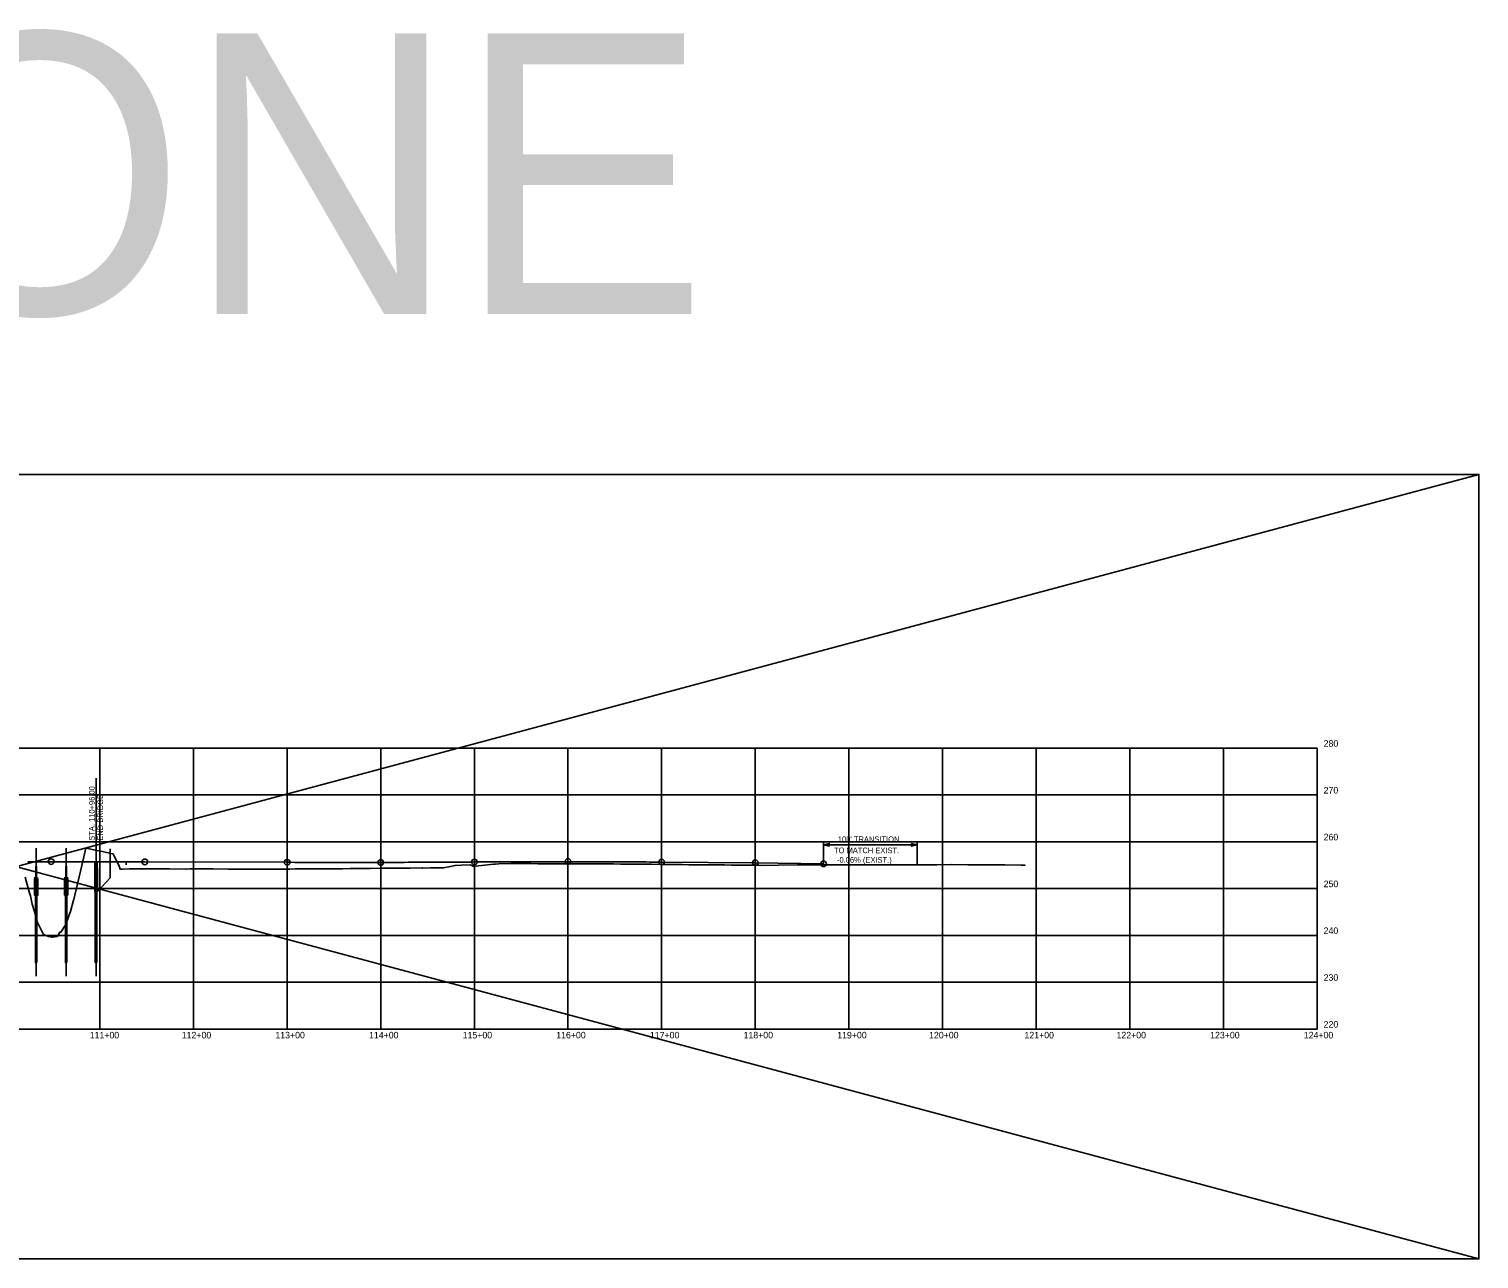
# Model space of a CAD drawing. Extents: x 1930770 to 1938778, y 596900 to 600561.
# Drawn here: x 1937230 to 1938778, y 598329 to 599642 of the extents above; entities that cross this region are included whole.
import ezdxf

# ---------------------------------------------------------------- set-up
doc = ezdxf.new("R2010")
doc.units = 0
for name, color, linetype in [('B_Centerline', 7, 'Continuous'), ('B_Pr_Beam_Line', 7, 'Continuous'), ('B_Pr_Cap_Beams', 7, 'Continuous'), ('B_Pr_Columns', 7, 'Continuous'), ('B_Pr_Deck', 7, 'Continuous'), ('BR_Pr_Cap_Beams', 7, 'Continuous'), ('Default', 7, 'Continuous'), ('S_CROSS_DRAIN_ANNOT', 7, 'Continuous'), ('S_DROP_INLET_ANNOT', 7, 'Continuous'), ('S_ELECTRIC_UTILITIES_ANNOT', 7, 'Continuous'), ('S_GAS_UTILITIES_ANNOT', 7, 'Continuous'), ('S_HIST_HIGH_WATER_ANNOT', 7, 'Continuous'), ('S_STORM_SEWER_ANNOT', 7, 'Continuous'), ('S_TELEPHONE_UTILITIES_ANNOT', 7, 'Continuous'), ('S_UTILITY_POLE_ANNOT', 7, 'Continuous'), ('S_WATER_UTILITIES_ANNOT', 7, 'Continuous')]:
    doc.layers.add(name, color=color, linetype=linetype)

msp = doc.modelspace()

# ---------------------------------------------------------------- linework, layer by layer
at = {"layer": 'B_Centerline'}
for p, q in [((1937237.2, 598631.1), (1937237.2, 598767.6)), ((1937269.2, 598631.1), (1937269.2, 598767.6)), ((1937301.2, 598631.1), (1937301.2, 598767.6))]:
    msp.add_line(p, q, dxfattribs=at)
at = {"layer": 'B_Pr_Beam_Line'}
msp.add_line((1937301.7, 598748.6), (1937301.7, 598736.9), dxfattribs=at)
at = {"layer": 'B_Pr_Cap_Beams'}
for p, q in [((1937237, 598736.6), (1937237, 598748.3)), ((1937237.5, 598736.6), (1937237.5, 598748.3)), ((1937269, 598736.8), (1937269, 598748.5)), ((1937269.5, 598736.8), (1937269.5, 598748.5))]:
    msp.add_line(p, q, dxfattribs=at)
for points in [[(1937235.5, 598735), (1937239, 598735), (1937239, 598717.5), (1937235.5, 598717.5)], [(1937267.5, 598735.2), (1937271, 598735.2), (1937271, 598717.7), (1937267.5, 598717.7)]]:
    msp.add_lwpolyline(points, close=True, dxfattribs=at)
at = {"layer": 'B_Pr_Columns'}
for p, q in [((1937236.4, 598696.6), (1937236.4, 598717.5)), ((1937238.1, 598690.3), (1937238.1, 598717.5)), ((1937268.4, 598696.8), (1937268.4, 598717.7)), ((1937270.1, 598690.5), (1937270.1, 598717.7)), ((1937300.4, 598646.2), (1937300.4, 598721.6)), ((1937302.1, 598721.6), (1937300.4, 598721.6)), ((1937302.1, 598646.2), (1937302.1, 598721.6)), ((1937236.4, 598646), (1937236.4, 598696.6)), ((1937268.4, 598646.2), (1937268.4, 598696.8)), ((1937238.1, 598646), (1937238.1, 598690.3)), ((1937270.1, 598646.2), (1937270.1, 598690.5)), ((1937238.1, 598679), (1937236.4, 598679)), ((1937270.1, 598679.2), (1937268.4, 598679.2))]:
    msp.add_line(p, q, dxfattribs=at)
at = {"layer": 'B_Pr_Deck'}
msp.add_line((1937301.2, 598749.6), (1937301.2, 598753.2), dxfattribs=at)
msp.add_lwpolyline([(1937316.2, 598753.2), (1937316.2, 598736.2), (1937302.7, 598721.6)], dxfattribs=at)
at = {"layer": 'BR_Pr_Cap_Beams'}
for p, q in [((1937235.9, 598735), (1937235.9, 598736.7)), ((1937236.6, 598735), (1937236.6, 598736.6)), ((1937237.9, 598735), (1937237.9, 598736.6)), ((1937238.6, 598735), (1937238.6, 598736.6)), ((1937267.9, 598735.2), (1937267.9, 598736.8)), ((1937268.6, 598735.2), (1937268.6, 598736.8)), ((1937269.9, 598735.2), (1937269.9, 598736.8)), ((1937270.6, 598735.2), (1937270.6, 598736.8))]:
    msp.add_line(p, q, dxfattribs=at)
at = {"layer": 'Default'}
for p, q in [((1937237.2, 598646), (1937238.2, 598646)), ((1937269.2, 598646.2), (1937270.2, 598646.2)), ((1937301.2, 598646.2), (1937302.2, 598646.2))]:
    msp.add_line(p, q, dxfattribs=at)
for points in [[(1937235.9, 598646.1), (1937237, 598646.1), (1937237.2, 598647.4), (1937237, 598644.8), (1937237.2, 598646)], [(1937267.9, 598646.2), (1937269, 598646.2), (1937269.2, 598647.6), (1937269, 598645), (1937269.2, 598646.2)], [(1937299.9, 598646.2), (1937301, 598646.2), (1937301.2, 598647.6), (1937301, 598645), (1937301.2, 598646.2)]]:
    msp.add_lwpolyline(points, dxfattribs=at)
at = {"layer": 'S_CROSS_DRAIN_ANNOT'}
for p, q in [((1938205.2, 598874.6), (1938205.2, 598874.3)), ((1938605.2, 598574.6), (1938605.2, 598874.6)), ((1937505.2, 598824.6), (1937505.2, 598824.3)), ((1937505.2, 598824.6), (1937505.2, 598824.3)), ((1938005.2, 598824.6), (1938005.2, 598824.2)), ((1935905.2, 598574.6), (1938605.2, 598574.6))]:
    msp.add_line(p, q, dxfattribs=at)
msp.add_lwpolyline([(1935652.7, 599166.8), (1938778.1, 599166.8), (1938778.1, 598329.1), (1935652.7, 598329.1)], close=True, dxfattribs=at)
at = {"layer": 'S_ELECTRIC_UTILITIES_ANNOT'}
for p, q in [((1937301.2, 598783.3), (1937301.2, 598842.5)), ((1937301.2, 598753.3), (1937301.2, 598783.3))]:
    msp.add_line(p, q, dxfattribs=at)
for centre in [(1937253.2, 598753.4), (1937353.2, 598753.1), (1937505.2, 598752.7), (1937605.2, 598752.4), (1937705.2, 598753), (1937805.2, 598753.6), (1937905.2, 598752.9), (1938005.2, 598752.2), (1938078.2, 598751.1)]:
    msp.add_circle(centre, 3, dxfattribs=at)
at = {"layer": 'S_GAS_UTILITIES_ANNOT'}
for p, q in [((1937302.2, 598753.2), (1937299.7, 598753.2)), ((1937299.7, 598721.6), (1937299.7, 598753.2)), ((1937302.2, 598753.2), (1937302.2, 598746.9)), ((1937302.2, 598746.9), (1937302.7, 598746.9)), ((1937302.7, 598721.6), (1937302.7, 598746.9))]:
    msp.add_line(p, q, dxfattribs=at)
for points in [[(1937299.7, 598721.6), (1937302.7, 598721.6), (1937302.7, 598721.6)], [(1937299.7, 598721.6), (1937302.7, 598721.6), (1937302.7, 598721.6)], [(1937302.7, 598721.6), (1937299.7, 598721.6), (1937299.7, 598721.6)]]:
    msp.add_lwpolyline(points, dxfattribs=at)
at = {"layer": 'S_HIST_HIGH_WATER_ANNOT'}
for p, q in [((1937353.2, 598753.1), (1937505.2, 598752.7)), ((1937905.2, 598752.9), (1938005.2, 598752.2)), ((1938005.2, 598752.2), (1938078.2, 598751.1))]:
    msp.add_line(p, q, dxfattribs=at)
for points in [[(1937228.2, 598753.3), (1937232.4, 598753.3), (1937236.6, 598753.3), (1937240.7, 598753.3), (1937244.9, 598753.3), (1937249.1, 598753.3), (1937257.4, 598753.3), (1937261.6, 598753.3), (1937265.7, 598753.3), (1937269.9, 598753.3), (1937274.1, 598753.3), (1937278.2, 598753.3), (1937282.4, 598753.3), (1937286.6, 598753.3), (1937290.7, 598753.3), (1937294.9, 598753.2), (1937299.1, 598753.2), (1937303.2, 598753.2), (1937307.4, 598753.2), (1937311.6, 598753.2), (1937315.7, 598753.2), (1937319.9, 598753.2), (1937324.1, 598753.2), (1937328.2, 598753.2), (1937332.4, 598753.2), (1937336.6, 598753.2), (1937340.7, 598753.2), (1937344.9, 598753.1), (1937349.1, 598753.1), (1937353.2, 598753.1)], [(1937505.2, 598752.7), (1937509.4, 598752.7), (1937513.6, 598752.6), (1937517.7, 598752.6), (1937521.9, 598752.6), (1937526.1, 598752.6), (1937530.2, 598752.6), (1937534.4, 598752.6), (1937538.6, 598752.6), (1937542.7, 598752.6), (1937546.9, 598752.6), (1937551.1, 598752.6), (1937555.2, 598752.6), (1937559.4, 598752.6), (1937563.6, 598752.6), (1937567.7, 598752.6), (1937571.9, 598752.6), (1937576.1, 598752.6), (1937580.2, 598752.6), (1937584.4, 598752.6), (1937588.6, 598752.6), (1937592.7, 598752.6), (1937596.9, 598752.6), (1937601.1, 598752.6), (1937609.4, 598752.6), (1937613.6, 598752.6), (1937617.7, 598752.6), (1937621.9, 598752.6), (1937626.1, 598752.6), (1937630.2, 598752.6), (1937634.4, 598752.7), (1937638.6, 598752.7), (1937642.7, 598752.7), (1937646.9, 598752.7), (1937651.1, 598752.7), (1937655.2, 598752.7), (1937659.4, 598752.7), (1937663.6, 598752.8), (1937667.7, 598752.8), (1937671.9, 598752.8), (1937676.1, 598752.8), (1937680.2, 598752.8), (1937684.4, 598752.9), (1937688.6, 598752.9), (1937692.7, 598752.9), (1937696.9, 598752.9), (1937701.1, 598752.9), (1937705.2, 598753)], [(1937705.2, 598753), (1937709.4, 598753), (1937713.6, 598753), (1937717.7, 598753), (1937721.9, 598753.1), (1937726.1, 598753.1), (1937730.2, 598753.1), (1937734.4, 598753.1), (1937738.6, 598753.1), (1937742.7, 598753.1), (1937746.9, 598753.2), (1937751.1, 598753.2), (1937755.2, 598753.2), (1937759.4, 598753.2), (1937763.6, 598753.2), (1937767.7, 598753.2), (1937771.9, 598753.2), (1937776.1, 598753.2), (1937780.2, 598753.2), (1937784.4, 598753.2), (1937788.6, 598753.2), (1937792.7, 598753.2), (1937796.9, 598753.2), (1937801.1, 598753.2), (1937809.4, 598753.2), (1937813.6, 598753.2), (1937817.7, 598753.2), (1937821.9, 598753.2), (1937826.1, 598753.2), (1937830.2, 598753.2), (1937834.4, 598753.2), (1937838.6, 598753.2), (1937842.7, 598753.2), (1937846.9, 598753.2), (1937851.1, 598753.2), (1937855.2, 598753.1), (1937859.4, 598753.1), (1937863.6, 598753.1), (1937867.7, 598753.1), (1937871.9, 598753.1), (1937876.1, 598753), (1937880.2, 598753), (1937884.4, 598753), (1937888.6, 598753), (1937892.7, 598752.9), (1937896.9, 598752.9), (1937901.1, 598752.9), (1937905.2, 598752.9)]]:
    msp.add_lwpolyline(points, dxfattribs=at)
at = {"layer": 'S_STORM_SEWER_ANNOT'}
for p, q in [((1938078.2, 598750.9), (1938078.2, 598774.3)), ((1938178.2, 598750.9), (1938178.2, 598774.3)), ((1938178.2, 598771.3), (1938078.2, 598771.3))]:
    msp.add_line(p, q, dxfattribs=at)
for points in [[(1938084.2, 598769.8), (1938078.2, 598771.3), (1938084.2, 598772.8)], [(1938172.2, 598772.8), (1938178.2, 598771.3), (1938172.2, 598769.8)]]:
    msp.add_lwpolyline(points, close=True, dxfattribs=at)
at = {"layer": 'S_TELEPHONE_UTILITIES_ANNOT'}
for p, q in [((1935652.7, 599166.8), (1938778.1, 598329.1)), ((1935652.7, 598329.1), (1938778.1, 599166.8)), ((1937301.2, 598771.1), (1937301.2, 598753.6)), ((1937316.2, 598753.2), (1937316.2, 598766.9)), ((1937333.2, 598749.8), (1937333.2, 598753.2))]:
    msp.add_line(p, q, dxfattribs=at)
at = {"layer": 'S_UTILITY_POLE_ANNOT'}
for p, q in [((1935905.2, 598874.6), (1938605.2, 598874.6)), ((1935905.2, 598874.6), (1938605.2, 598874.6)), ((1937305.2, 598574.6), (1937305.2, 598874.6)), ((1937405.2, 598574.6), (1937405.2, 598874.6)), ((1937505.2, 598574.6), (1937505.2, 598874.6)), ((1937605.2, 598574.6), (1937605.2, 598874.6)), ((1937705.2, 598574.6), (1937705.2, 598874.6)), ((1937805.2, 598574.6), (1937805.2, 598874.6)), ((1937905.2, 598574.6), (1937905.2, 598874.6)), ((1938005.2, 598574.6), (1938005.2, 598874.6)), ((1938105.2, 598574.6), (1938105.2, 598874.6)), ((1938205.2, 598574.6), (1938205.2, 598874.6)), ((1938305.2, 598574.6), (1938305.2, 598874.6)), ((1938405.2, 598574.6), (1938405.2, 598874.6)), ((1938505.2, 598574.6), (1938505.2, 598874.6)), ((1935905.2, 598824.6), (1938605.2, 598824.6)), ((1935905.2, 598774.6), (1938605.2, 598774.6)), ((1935905.2, 598724.6), (1938605.2, 598724.6)), ((1935905.2, 598674.6), (1938605.2, 598674.6)), ((1935905.2, 598624.6), (1938605.2, 598624.6))]:
    msp.add_line(p, q, dxfattribs=at)
at = {"layer": 'S_WATER_UTILITIES_ANNOT'}
msp.add_lwpolyline([(1937225.5, 598736.8), (1937229.8, 598721.2), (1937231, 598716.8), (1937233.1, 598708), (1937236.7, 598695.5), (1937238.4, 598689.2), (1937243.4, 598679), (1937245, 598675.6), (1937249.7, 598673.7), (1937250.3, 598673.6), (1937250.8, 598673.4), (1937251.2, 598673.4), (1937253.9, 598672.7), (1937254.6, 598672.6), (1937259.9, 598673.6), (1937260.2, 598674.2), (1937262.6, 598678.2), (1937263.6, 598678), (1937269, 598686.1), (1937272.6, 598696.7), (1937273.8, 598700.2), (1937277.1, 598712.1), (1937277.2, 598711.5), (1937286, 598749.1), (1937290.1, 598767.7), (1937294, 598766.9), (1937301.5, 598765.3), (1937304.9, 598764.9), (1937315.5, 598762.5), (1937317.1, 598762.1), (1937319.4, 598761.8), (1937325.8, 598748.7), (1937326.8, 598745.3), (1937329.5, 598745.5), (1937336.9, 598745.6), (1937347.7, 598745.7), (1937350.2, 598745.7), (1937358.3, 598745.7), (1937371.1, 598745.6), (1937372.6, 598745.6), (1937373.9, 598745.7), (1937379.7, 598745.6), (1937397, 598745.5), (1937397.2, 598745.5), (1937397.4, 598745.5), (1937401.2, 598745.6), (1937402.2, 598745.6), (1937407.6, 598745.7), (1937407.9, 598745.7), (1937422.6, 598745.6), (1937424.8, 598745.6), (1937426.1, 598745.6), (1937442.5, 598745.5), (1937444, 598745.5), (1937445.1, 598745.5), (1937460.5, 598745.4), (1937465.5, 598745.4), (1937474.5, 598745.3), (1937479.7, 598745.3), (1937486.9, 598745.4), (1937495.2, 598745.5), (1937502.7, 598745.4), (1937508.3, 598745.5), (1937513.8, 598745.6), (1937521.6, 598745.7), (1937529.7, 598745.8), (1937535, 598745.8), (1937541.6, 598745.8), (1937542, 598745.8), (1937551.2, 598745.8), (1937562.5, 598745.8), (1937564.3, 598745.8), (1937572.6, 598745.9), (1937583.7, 598746.1), (1937585.9, 598746.1), (1937594, 598746.2), (1937604.8, 598746.4), (1937607.5, 598746.4), (1937615.4, 598746.4), (1937626.8, 598746.5), (1937628.7, 598746.4), (1937636.9, 598746.5), (1937649, 598746.6), (1937649.9, 598746.5), (1937658.3, 598746.6), (1937670.4, 598746.6), (1937672.4, 598746.6), (1937679.7, 598748.3), (1937684.6, 598749.4), (1937691, 598749.6), (1937701, 598750), (1937701.1, 598750), (1937704.7, 598748.2), (1937709.5, 598748.8), (1937722.6, 598750.2), (1937725.7, 598750.6), (1937727.6, 598750.8), (1937731.3, 598751.2), (1937744, 598751.3), (1937744, 598751.3), (1937749.5, 598751.3), (1937761.2, 598751.3), (1937765.4, 598751.3), (1937773, 598751.2), (1937778.6, 598751.2), (1937786.9, 598751.1), (1937795.2, 598751.1), (1937796.2, 598751.1), (1937796.3, 598751.1), (1937808.3, 598751.1), (1937815, 598751.1), (1937817.6, 598751.1), (1937829.7, 598751.1), (1937833.9, 598751.1), (1937838.8, 598751.1), (1937851.1, 598751), (1937853.9, 598751), (1937861.2, 598750.8), (1937869.8, 598750.7), (1937872.6, 598750.7), (1937883.5, 598750.6), (1937894, 598750.5), (1937894.3, 598750.5), (1937905.3, 598750.4), (1937915.4, 598750.3), (1937918.1, 598750.3), (1937927.2, 598750.2), (1937934.4, 598750.1), (1937936.8, 598750.1), (1937947.3, 598750), (1937953.3, 598749.9), (1937958.3, 598749.9), (1937967.5, 598749.9), (1937972.3, 598749.8), (1937979.7, 598749.7), (1937988.2, 598749.7), (1937991.9, 598749.6), (1938001.1, 598749.5), (1938008.9, 598749.5), (1938011.7, 598749.4), (1938030.1, 598749.7), (1938050.2, 598749.9), (1938051.4, 598749.9), (1938073.1, 598750), (1938073.8, 598750), (1938074.4, 598750), (1938096.2, 598750.1), (1938096.3, 598750.1), (1938114.3, 598750.1), (1938114.4, 598750.1), (1938132.4, 598750.1), (1938132.4, 598750.1), (1938141.7, 598750.1), (1938150.4, 598750.1), (1938150.4, 598750.1), (1938168.4, 598750), (1938168.5, 598750), (1938191.5, 598750.1), (1938191.6, 598750.1), (1938191.6, 598750.1), (1938199.2, 598750.1), (1938214.6, 598750.2), (1938214.6, 598750.2), (1938232.2, 598750.1), (1938232.2, 598750.1), (1938249.7, 598750), (1938249.8, 598750), (1938271.6, 598749.9), (1938289.3, 598749.7), (1938293.4, 598749.7), (1938293.4, 598749.7)], dxfattribs=at)

# ---------------------------------------------------------------- texts
at = {"layer": 'S_CROSS_DRAIN_ANNOT'}
msp.add_text('OLD ONE', height=300, dxfattribs=at).set_placement((1936148.6, 599338))
at = {"layer": 'S_DROP_INLET_ANNOT'}
for s, p in [('280', (1938612.2, 598876.1)), ('280', (1938612.2, 598876.1)), ('270', (1938612.2, 598826.1)), ('260', (1938612.2, 598776.1)), ('250', (1938612.2, 598726.1)), ('240', (1938612.2, 598676.1)), ('230', (1938612.2, 598626.1)), ('111+00', (1937294.4, 598564.6)), ('112+00', (1937392.7, 598564.6)), ('113+00', (1937492.7, 598564.6)), ('114+00', (1937592.7, 598564.6)), ('115+00', (1937692.7, 598564.6)), ('116+00', (1937792.6, 598564.6)), ('117+00', (1937892.7, 598564.6)), ('118+00', (1937992.7, 598564.6)), ('119+00', (1938092.7, 598564.6)), ('120+00', (1938190.8, 598564.6)), ('121+00', (1938292.7, 598564.6)), ('122+00', (1938391, 598564.6)), ('123+00', (1938491, 598564.6)), ('124+00', (1938591, 598564.6)), ('220', (1938612.2, 598576.1))]:
    msp.add_text(s, height=7, dxfattribs=at).set_placement(p)
at = {"layer": 'S_ELECTRIC_UTILITIES_ANNOT'}
for s, rotation, p in [('STA. 110+96.00', 90, (1937299.7, 598775.7)), ('END BRIDGE', 90, (1937308.7, 598775.7)), ('-0.06% (EXIST.)', 359.8731, (1938092.5, 598752.3))]:
    msp.add_text(s, height=6, rotation=rotation, dxfattribs=at).set_placement(p)
at = {"layer": 'S_STORM_SEWER_ANNOT'}
for s, p in [("100' TRANSITION", (1938093.4, 598774.3)), ('TO MATCH EXIST.', (1938089.3, 598762.4))]:
    msp.add_text(s, height=6, rotation=0.0048, dxfattribs=at).set_placement(p)

doc.saveas('drawing.dxf')
